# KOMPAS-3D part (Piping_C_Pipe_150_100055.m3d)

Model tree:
1. Plane XY
2. Plane ZX
3. Plane ZY
4. X Axis
5. Y Axis
6. Z Axis
7. Origin
8. Path  (labels: Отвод 90 Dy 150; Труба Dy 150; Тройник Dy 150)
9. Plane of section
10. Section of pipe
11. Pipe
     Толщина стенки 1 = 1

Referenced files in C:\Program Files\ASCON\KOMPAS-3D V10\Libs\Piping\Models\Tanks\: Tanks.a3d
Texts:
  Pipe Dn 150
  Steel ASTM A295
  Three Point Plane
  Plane at Angle
  Line and Point Plane
  Axis through Two Vertices
  Axis of Feature
  Axis of Conical Surface
  Axis through Edge
  Приклеить элемент выдавливания
  Приклеить элемент вращения
  Приклеить кинематический элемент
  Приклеить элемент по сечениям
  Trim by Surface
  Trim by Sketch
  Feature with No History
  Intersection Axis of Two Planes
  Two Line Plane
  Line and Face Plane
  Bend by line
  Hole in sheet body
  Cut in sheet body
  Point in CM
  Linear Dimension from Line to Point
  Surface Finish Symbol
  Geometric Tolerance Symbol
  Текст на чертеже
  Линия-выноска #1
  Линия-выноска #2
  Линия-выноска #3
  Отклонения формы и база
  Марка координационной оси
  Марка/позиционное обозначение с линией-выноской
  Марка/позиционное обозначение на линии
  Марка/позиционное обозначение без линии-выноски
  Отвод 90 Dy 150
  Труба Dy 150
  Тройник Dy 150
